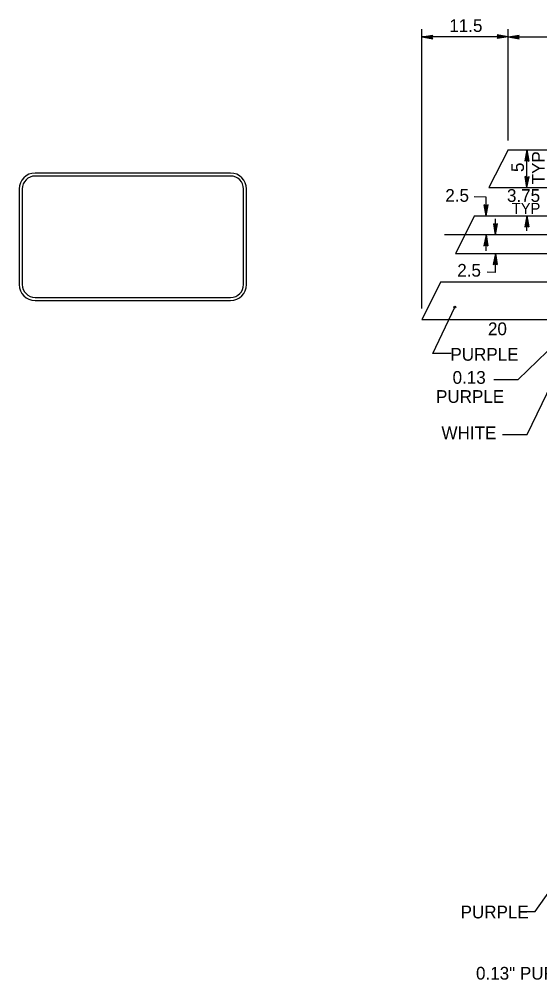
# Model space of a CAD drawing. Extents: x 10268197 to 10269179, y 2141503 to 2142677.
# Drawn here: x 10268439.2 to 10268467.9, y 2142119.1 to 2142171.9 of the extents above; entities that cross this region are included whole.
import ezdxf

# ---------------------------------------------------------------- set-up
doc = ezdxf.new("R2010")
doc.units = 0
for name, color, linetype in [('1', 7, 'Continuous'), ('2', 7, 'Continuous'), ('21', 7, 'Continuous'), ('GSOutline', 7, 'Continuous')]:
    doc.layers.add(name, color=color, linetype=linetype)

msp = doc.modelspace()

# ---------------------------------------------------------------- linework, layer by layer
at = {"layer": '1'}
for p, q in [((10268461.378, 2142156.016), (10268461.378, 2142171.353)), ((10268466.124, 2142170.939), (10268461.378, 2142170.939)), ((10268466.124, 2142165.239), (10268466.124, 2142171.353)), ((10268466.124, 2142170.939), (10268466.729, 2142171.035)), ((10268466.124, 2142170.939), (10268466.704, 2142170.98)), ((10268466.124, 2142170.939), (10268491.278, 2142170.939)), ((10268466.124, 2142170.939), (10268466.726, 2142170.822)), ((10268466.124, 2142170.939), (10268466.703, 2142170.879)), ((10268466.681, 2142170.929), (10268466.729, 2142171.035)), ((10268466.726, 2142170.822), (10268466.681, 2142170.929)), ((10268467.16, 2142164.721), (10268467.043, 2142164.119)), ((10268467.16, 2142164.721), (10268467.099, 2142164.142)), ((10268467.16, 2142162.651), (10268467.16, 2142164.721)), ((10268467.16, 2142164.721), (10268467.256, 2142164.115)), ((10268467.16, 2142164.721), (10268467.2, 2142164.142)), ((10268467.043, 2142164.119), (10268467.15, 2142164.164)), ((10268467.15, 2142164.164), (10268467.256, 2142164.115)), ((10268467.16, 2142162.651), (10268467.063, 2142163.256)), ((10268467.169, 2142163.208), (10268467.063, 2142163.256)), ((10268467.16, 2142162.651), (10268467.118, 2142163.23)), ((10268467.16, 2142162.651), (10268467.276, 2142163.252)), ((10268467.16, 2142162.651), (10268467.22, 2142163.229)), ((10268467.276, 2142163.252), (10268467.169, 2142163.208)), ((10268464.908, 2142162.133), (10268464.252, 2142162.138)), ((10268464.908, 2142161.098), (10268464.908, 2142162.133)), ((10268464.908, 2142161.098), (10268464.811, 2142161.703)), ((10268464.917, 2142161.656), (10268464.811, 2142161.703)), ((10268464.908, 2142161.098), (10268464.867, 2142161.678)), ((10268464.908, 2142161.098), (10268465.024, 2142161.7)), ((10268464.908, 2142161.098), (10268464.968, 2142161.676)), ((10268465.024, 2142161.7), (10268464.917, 2142161.656)), ((10268465.425, 2142160.063), (10268465.425, 2142160.943)), ((10268467.16, 2142161.098), (10268467.043, 2142160.497)), ((10268467.16, 2142161.098), (10268467.099, 2142160.52)), ((10268467.16, 2142160.27), (10268467.16, 2142161.098)), ((10268467.16, 2142161.098), (10268467.256, 2142160.493)), ((10268467.16, 2142161.098), (10268467.2, 2142160.519)), ((10268465.425, 2142160.063), (10268465.329, 2142160.668)), ((10268465.434, 2142160.621), (10268465.329, 2142160.668)), ((10268465.425, 2142160.063), (10268465.384, 2142160.643)), ((10268465.425, 2142160.063), (10268465.542, 2142160.664)), ((10268465.425, 2142160.063), (10268465.486, 2142160.641)), ((10268465.542, 2142160.664), (10268465.434, 2142160.621)), ((10268467.043, 2142160.497), (10268467.15, 2142160.541)), ((10268467.15, 2142160.541), (10268467.256, 2142160.493)), ((10268469.356, 2142160.063), (10268462.621, 2142160.063)), ((10268464.908, 2142160.063), (10268464.791, 2142159.462)), ((10268464.908, 2142160.063), (10268464.847, 2142159.485)), ((10268464.908, 2142159.183), (10268464.908, 2142160.063)), ((10268464.908, 2142160.063), (10268465.004, 2142159.458)), ((10268464.908, 2142160.063), (10268464.948, 2142159.483)), ((10268464.791, 2142159.462), (10268464.898, 2142159.506)), ((10268464.898, 2142159.506), (10268465.004, 2142159.458)), ((10268465.425, 2142159.028), (10268465.308, 2142158.426)), ((10268465.425, 2142159.028), (10268465.365, 2142158.45)), ((10268465.425, 2142157.993), (10268465.425, 2142159.028)), ((10268465.425, 2142159.028), (10268465.521, 2142158.423)), ((10268465.425, 2142159.028), (10268465.465, 2142158.449)), ((10268465.308, 2142158.426), (10268465.416, 2142158.471)), ((10268465.416, 2142158.471), (10268465.521, 2142158.423)), ((10268465.425, 2142157.993), (10268464.967, 2142157.997)), ((10268461.984, 2142153.541), (10268463.189, 2142156.09)), ((10268467.17, 2142149.083), (10268469.706, 2142154.341)), ((10268462.992, 2142153.541), (10268461.984, 2142153.541)), ((10268466.668, 2142152.098), (10268468.262, 2142153.645)), ((10268465.331, 2142152.098), (10268466.668, 2142152.098)), ((10268465.813, 2142149.093), (10268467.17, 2142149.093)), ((10268467.601, 2142122.868), (10268469.358, 2142125.347)), ((10268466.987, 2142122.868), (10268467.601, 2142122.868))]:
    msp.add_line(p, q, dxfattribs=at)
msp.add_circle((10268463.189, 2142156.091), 0.0518, dxfattribs=at)
at = {"layer": '2'}
for p, q in [((10268466.124, 2142164.721), (10268465.07, 2142162.651)), ((10268466.124, 2142164.721), (10268469.658, 2142164.721)), ((10268465.07, 2142162.651), (10268468.638, 2142162.651)), ((10268464.278, 2142161.098), (10268463.223, 2142159.028)), ((10268464.278, 2142161.098), (10268468.289, 2142161.098)), ((10268463.223, 2142159.028), (10268468.289, 2142159.028)), ((10268462.432, 2142157.475), (10268461.378, 2142155.405)), ((10268462.432, 2142157.475), (10268468.638, 2142157.475)), ((10268461.378, 2142155.405), (10268469.658, 2142155.405))]:
    msp.add_line(p, q, dxfattribs=at)
at = {"layer": '21'}
for p, q in [((10268461.378, 2142170.939), (10268461.983, 2142171.035)), ((10268461.378, 2142170.939), (10268461.958, 2142170.98)), ((10268461.378, 2142170.939), (10268461.979, 2142170.822)), ((10268461.378, 2142170.939), (10268461.956, 2142170.879)), ((10268461.935, 2142170.929), (10268461.983, 2142171.035)), ((10268461.979, 2142170.822), (10268461.935, 2142170.929)), ((10268465.567, 2142170.949), (10268465.519, 2142170.843)), ((10268466.124, 2142170.939), (10268465.519, 2142170.843)), ((10268466.124, 2142170.939), (10268465.523, 2142171.056)), ((10268465.523, 2142171.056), (10268465.567, 2142170.949)), ((10268466.124, 2142170.939), (10268465.545, 2142170.899)), ((10268466.124, 2142170.939), (10268465.546, 2142171))]:
    msp.add_line(p, q, dxfattribs=at)
at = {"layer": 'GSOutline'}
for p, q in [((10268450.867, 2142163.455), (10268440.115, 2142163.455)), ((10268450.867, 2142163.288), (10268440.115, 2142163.288)), ((10268439.24, 2142162.58), (10268439.24, 2142157.329)), ((10268439.407, 2142162.58), (10268439.407, 2142157.329)), ((10268451.576, 2142157.329), (10268451.576, 2142162.58)), ((10268451.742, 2142157.329), (10268451.742, 2142162.58)), ((10268440.115, 2142156.62), (10268450.867, 2142156.62)), ((10268440.115, 2142156.454), (10268450.867, 2142156.454))]:
    msp.add_line(p, q, dxfattribs=at)
for centre, radius, start, end in [((10268440.115, 2142162.58), 0.875, 90, 180), ((10268440.115, 2142162.58), 0.708, 90, 180), ((10268450.867, 2142162.58), 0.875, 0, 90), ((10268450.867, 2142162.58), 0.708, 0, 90), ((10268440.115, 2142157.329), 0.875, 180, 270), ((10268440.115, 2142157.329), 0.708, 180, 270), ((10268450.867, 2142157.329), 0.875, 270, 0), ((10268450.867, 2142157.329), 0.708, 270, 0)]:
    msp.add_arc(centre, radius, start, end, dxfattribs=at)

# ---------------------------------------------------------------- texts
at = {"layer": '1'}
for s, height, p in [('11.5', 0.7, (10268462.89, 2142171.208)), ('2.5', 0.7, (10268462.668, 2142161.874)), ('3.75', 0.7, (10268466.06, 2142161.869)), ('TYP', 0.6037, (10268466.325, 2142161.208)), ('2.5', 0.7, (10268463.326, 2142157.759)), ('20', 0.7, (10268465.015, 2142154.542)), ('PURPLE', 0.7, (10268462.95, 2142153.139)), ('0.13', 0.7, (10268463.07, 2142151.871)), ('PURPLE', 0.7, (10268462.161, 2142150.821)), ('WHITE', 0.7, (10268462.458, 2142148.826)), ('PURPLE', 0.7, (10268463.509, 2142122.489)), ('0.13" PURPLE', 0.7, (10268464.357, 2142119.125))]:
    msp.add_text(s, height=height, dxfattribs=at).set_placement(p)
for s, p in [('TYP', (10268468.135, 2142162.831)), ('5', (10268466.994, 2142163.507))]:
    msp.add_text(s, height=0.7, rotation=90, dxfattribs=at).set_placement(p)

doc.saveas('drawing.dxf')
